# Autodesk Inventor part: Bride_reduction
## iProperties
Shininess: 64.0
Length Units: 11269
Angle Units: 11279
Time Units: 11290
Mass Units: 11283
Length Display Precision: 3
Angle Display Precision: 2
Compacted: True
Part Number: Bride_reduction
Document SubType Name: Modeling
Created: 2008-02
Material: Par défaut
Designer: Pascal
Density: 1 g/cm^3
Density: 0.0
Volumn: 0.0
Area: 0.0
PropertySet Name: Model Information
Control State: 0
Master: False
Checked Out: False
MATIERE_PIECE: X2CrNi 18-11
OBSERVATIONS: ep. 8
DESIGNATION: Bride DN 150
Author: Pascal
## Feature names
1. Extrusion1
2. Extrusion2
3. Réseau circulaire1 [Circular Pattern]
